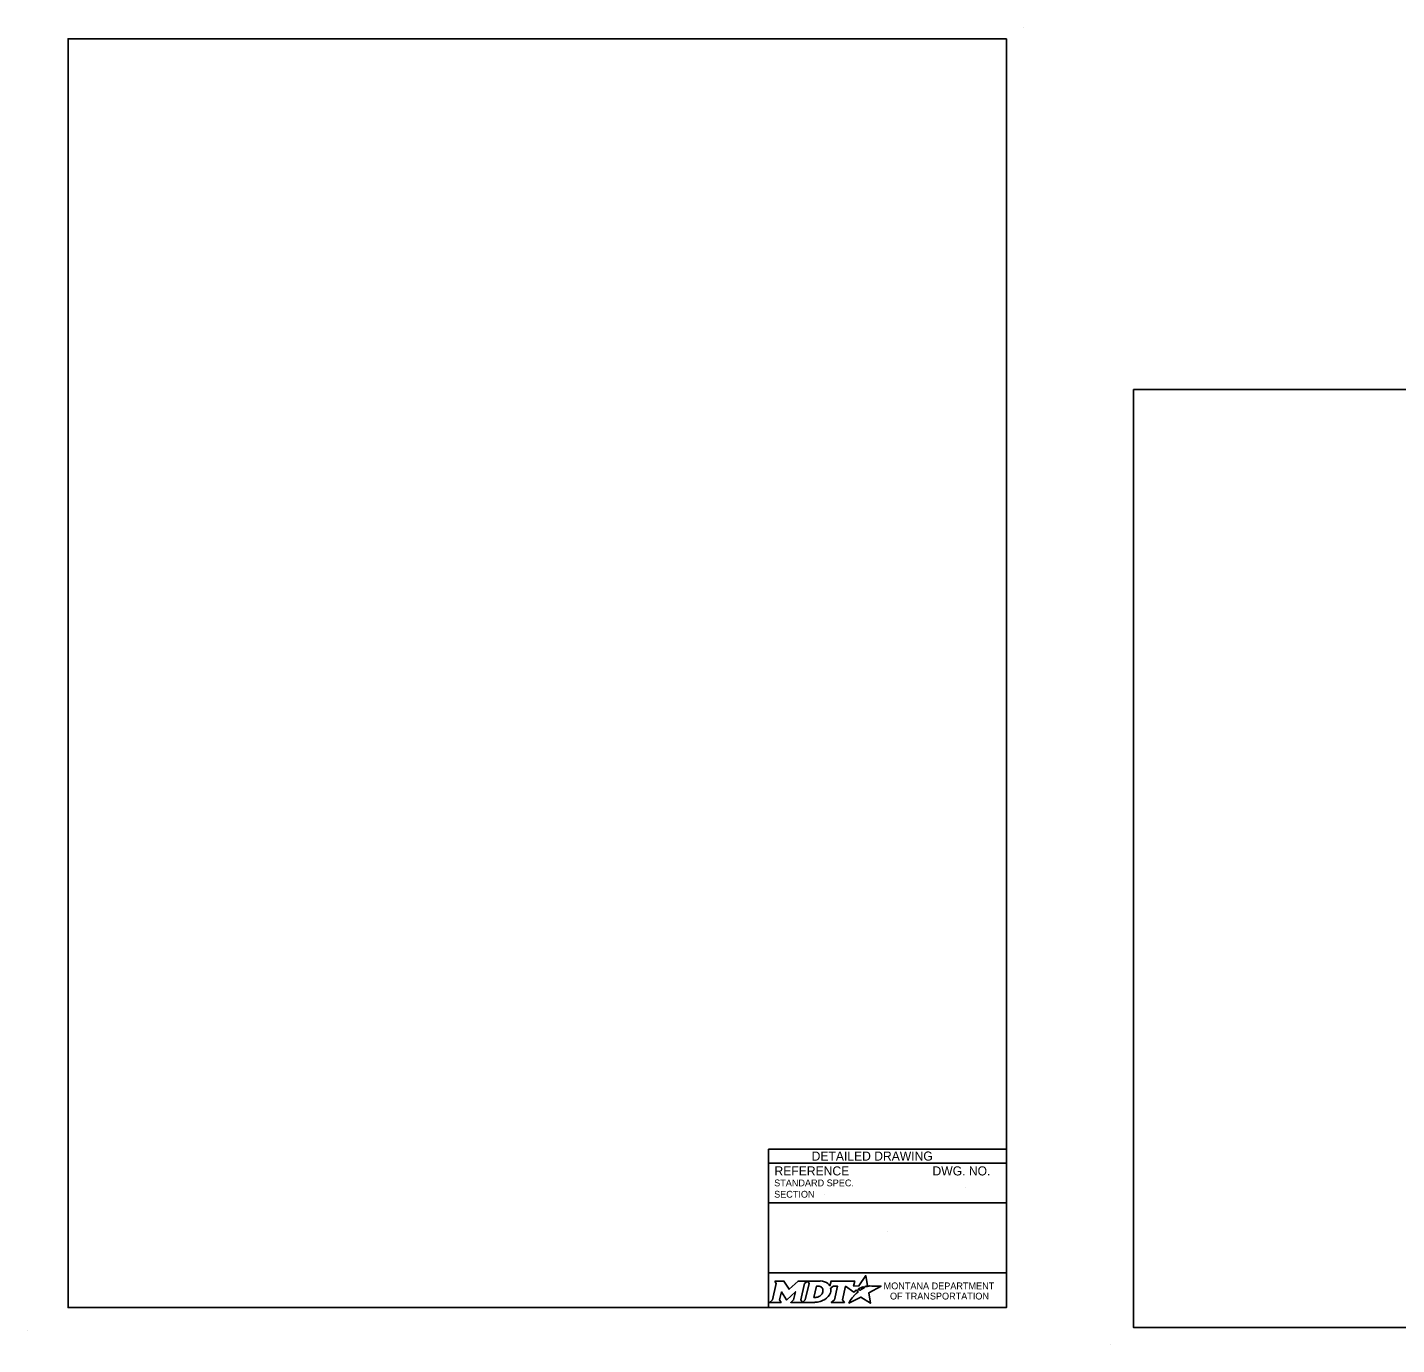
# Model space of a CAD drawing. Extents: x 49991.4 to 50028.3, y 49987.6 to 50011.4.
# Drawn here: x 49999.98 to 50012.06, y 49999.74 to 50011.36 of the extents above; entities that cross this region are included whole.
import ezdxf

# ---------------------------------------------------------------- set-up
doc = ezdxf.new("R2010")
doc.units = 0
doc.layers.add('Level 1', color=7, linetype='Continuous')
doc.layers.add('Level 2', color=7, linetype='Continuous')

msp = doc.modelspace()

# ---------------------------------------------------------------- linework, layer by layer
at = {"layer": 'Level 1'}
for p, q in [((50008.765, 50011.363), (50008.765, 50011.363)), ((49999.977, 49999.862), (49999.977, 49999.862)), ((50009.537, 49999.736), (50009.537, 49999.736))]:
    msp.add_line(p, q, dxfattribs=at)
for points in [[(50008.615, 50011.263), (50000.336, 50011.263), (50000.336, 50000.062), (50008.615, 50000.062)], [(50020.938, 50008.165), (50009.737, 50008.165), (50009.737, 49999.886), (50020.938, 49999.886)]]:
    msp.add_lwpolyline(points, close=True, dxfattribs=at)
at = {"layer": 'Level 2'}
for p, q in [((50008.615, 50001.462), (50006.515, 50001.462)), ((50006.515, 50001.462), (50006.515, 50000.062)), ((50008.615, 50001.337), (50006.515, 50001.337)), ((50008.251, 50001.122), (50008.251, 50001.122)), ((50007.009, 50001.063), (50007.009, 50001.063)), ((50008.615, 50000.987), (50006.515, 50000.987)), ((50007.565, 50000.738), (50007.565, 50000.738)), ((50008.615, 50000.369), (50006.515, 50000.369))]:
    msp.add_line(p, q, dxfattribs=at)
for points in [[(50006.57, 50000.297), (50006.584, 50000.274), (50006.551, 50000.131), (50006.525, 50000.108), (50006.627, 50000.108), (50006.613, 50000.131), (50006.629, 50000.201), (50006.673, 50000.132), (50006.678, 50000.132), (50006.753, 50000.202), (50006.737, 50000.13), (50006.712, 50000.108), (50006.814, 50000.108), (50006.8, 50000.132), (50006.833, 50000.274)], [(50006.833, 50000.274), (50006.859, 50000.297), (50006.776, 50000.297), (50006.697, 50000.224), (50006.652, 50000.297), (50006.57, 50000.297)], [(50006.972, 50000.297), (50006.859, 50000.297), (50006.873, 50000.275), (50006.839, 50000.131), (50006.814, 50000.108), (50006.925, 50000.108)], [(50007.377, 50000.245), (50007.367, 50000.25), (50007.378, 50000.253), (50007.39, 50000.255), (50007.373, 50000.345), (50007.313, 50000.254), (50007.266, 50000.253), (50007.276, 50000.297), (50007.067, 50000.297), (50007.057, 50000.255), (50007.051, 50000.263)], [(50006.996, 50000.211), (50006.995, 50000.203), (50006.992, 50000.193), (50006.988, 50000.185), (50006.982, 50000.178), (50006.976, 50000.171), (50006.968, 50000.164), (50006.959, 50000.16), (50006.95, 50000.156), (50006.941, 50000.154), (50006.932, 50000.153), (50006.916, 50000.153), (50006.94, 50000.253), (50006.956, 50000.253), (50006.963, 50000.252), (50006.971, 50000.25), (50006.977, 50000.247), (50006.983, 50000.243), (50006.988, 50000.238), (50006.992, 50000.232), (50006.995, 50000.226), (50006.996, 50000.218), (50006.996, 50000.215), (50006.996, 50000.211)], [(50007.064, 50000.238), (50007.088, 50000.251), (50007.125, 50000.251), (50007.097, 50000.131), (50007.069, 50000.108), (50007.185, 50000.108), (50007.168, 50000.131), (50007.196, 50000.251), (50007.268, 50000.2), (50007.289, 50000.215), (50007.309, 50000.204)], [(50007.253, 50000.148), (50007.237, 50000.124), (50007.233, 50000.116), (50007.227, 50000.107), (50007.225, 50000.103), (50007.33, 50000.156), (50007.414, 50000.101), (50007.401, 50000.194), (50007.508, 50000.252), (50007.458, 50000.253), (50007.428, 50000.253), (50007.407, 50000.254), (50007.401, 50000.252), (50007.396, 50000.251), (50007.387, 50000.249), (50007.377, 50000.245)], [(50007.267, 50000.164), (50007.267, 50000.164)], [(50007.327, 50000.217), (50007.324, 50000.215), (50007.306, 50000.225), (50007.316, 50000.231), (50007.32, 50000.233), (50007.329, 50000.237), (50007.335, 50000.239), (50007.343, 50000.243), (50007.35, 50000.245), (50007.362, 50000.238), (50007.358, 50000.236), (50007.353, 50000.233), (50007.349, 50000.231), (50007.344, 50000.228), (50007.342, 50000.227), (50007.339, 50000.225), (50007.337, 50000.224), (50007.334, 50000.222), (50007.332, 50000.221), (50007.329, 50000.219), (50007.327, 50000.217)], [(50006.97, 50000.116), (50006.979, 50000.118), (50006.992, 50000.124), (50007.012, 50000.135)]]:
    msp.add_lwpolyline(points, dxfattribs=at)
for centre, radius, start, end in [((50006.951, 50000.236), 0.118, 300.9103, 339.1383), ((50006.995, 50000.219), 0.0709, 339.5329, 15.8582)]:
    msp.add_arc(centre, radius, start, end, dxfattribs=at)
for centre, major_axis, ratio, start_param, end_param in [((50006.97, 50000.25), (0.0834, -0.0037), 0.568097, 0.61298, 1.570796), ((50007.026, 50000.257), (0.0361, -0.0295), 0.469099, 1.225588, 1.570796), ((50007.26, 50000.156), (-0.00694, -0.00806), 0.008222, 0, 3.137361), ((50007.276, 50000.174), (-0.0098, -0.0102), 0.016458, 3.141593, 6.279097), ((50007.297, 50000.194), (-0.0112, -0.0097), 0.021651, 3.157348, 6.283185), ((50006.925, 50000.257), (0, 0.148), 0.987302, 3.139398, 3.456847)]:
    msp.add_ellipse(centre, major_axis=major_axis, ratio=ratio, start_param=start_param, end_param=end_param, dxfattribs=at)

# ---------------------------------------------------------------- texts
for s, height, p in [('DETAILED DRAWING', 0.0799, (50006.896, 50001.36)), ('REFERENCE', 0.08, (50006.568, 50001.229)), ('DWG. NO.', 0.08, (50007.962, 50001.229)), ('STANDARD SPEC.', 0.06, (50006.565, 50001.133)), ('SECTION', 0.06, (50006.565, 50001.033)), ('MONTANA DEPARTMENT', 0.06, (50007.531, 50000.224)), ('OF TRANSPORTATION', 0.06, (50007.587, 50000.134))]:
    msp.add_text(s, height=height, dxfattribs=at).set_placement(p)

doc.saveas('drawing.dxf')
